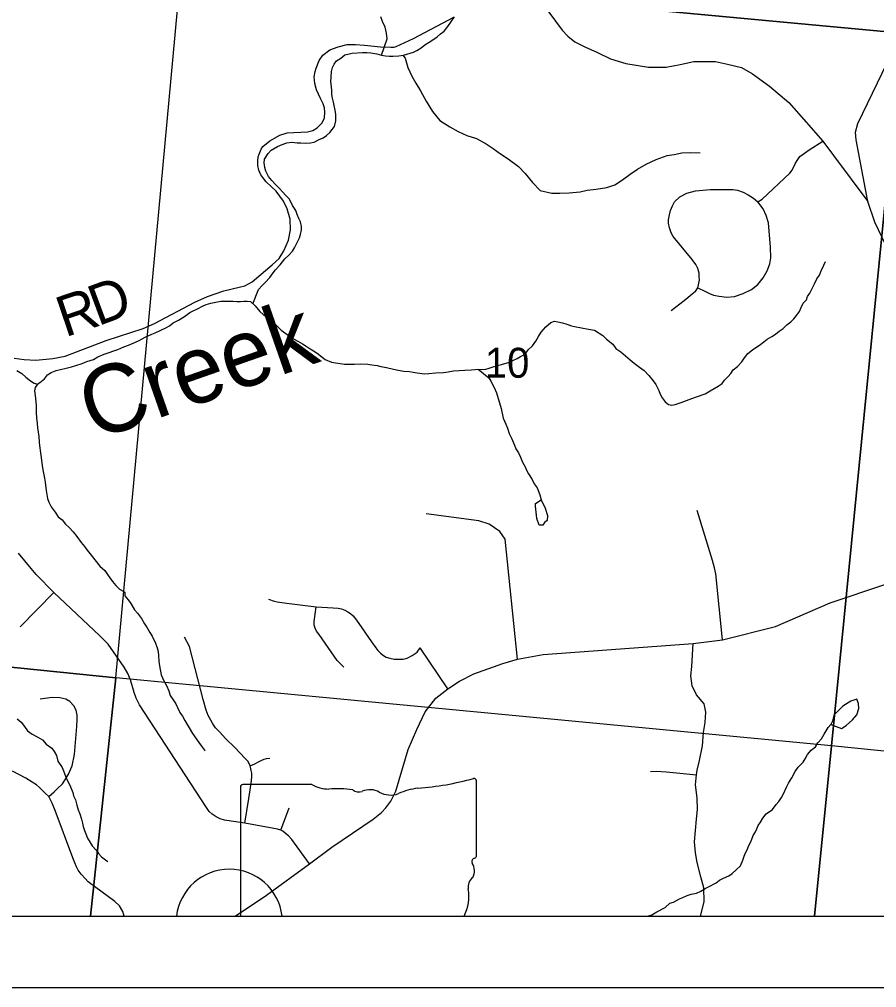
# Model space of a CAD drawing. Extents: x 0 to 34, y 0 to 22.
# Drawn here: x 2.941 to 4.14, y 14 to 15.353 of the extents above; entities that cross this region are included whole.
import ezdxf

# ---------------------------------------------------------------- set-up
doc = ezdxf.new("R2010")
doc.units = 0
for name, color, linetype in [('Default', 7, 'Continuous'), ('GM_X_County_Road', 7, 'Continuous'), ('GM_X_County_Road_Text', 7, 'Continuous'), ('GM_X_Major_Lake', 7, 'Continuous'), ('GM_X_Minor_Lake', 7, 'Continuous'), ('GM_X_Minor_River', 7, 'Continuous'), ('GM_X_Minor_River_Text', 7, 'Continuous'), ('GM_X_Section', 7, 'Continuous'), ('GM_X_Section_Text', 7, 'Continuous'), ('GM_X_State_Location', 7, 'Continuous'), ('GM_X_State_Route', 7, 'Continuous'), ('GM_X_Township_Road', 7, 'Continuous'), ('GM_X_Unincorporated_Text', 7, 'Continuous'), ('SH_Data', 7, 'Continuous')]:
    doc.layers.add(name, color=color, linetype=linetype)

msp = doc.modelspace()

# ---------------------------------------------------------------- linework, layer by layer
at = {"layer": 'Default'}
for points in [[(2.1, 14.8697), (2.1, 14.5322), (3.0761, 14.4328), (3.1681, 15.4277), (2.1629, 15.5646)], [(2.1, 14.5322), (2.1, 14.1), (3.0409, 14.1), (3.0761, 14.4328)], [(3.0409, 14.1), (4.0529, 14.1), (4.0766, 14.3377), (3.0761, 14.4328)], [(4.0529, 14.1), (5.0677, 14.1), (5.0822, 14.236), (4.0766, 14.3377)]]:
    msp.add_lwpolyline(points, close=True, dxfattribs=at)
at = {"layer": 'GM_X_County_Road'}
for points in [[(3.672, 15.3757), (3.7001, 15.338), (3.708, 15.3295), (3.7178, 15.3218), (3.7316, 15.3145), (3.7492, 15.3065), (3.7674, 15.2977), (3.789, 15.2914), (3.8205, 15.2861), (3.8455, 15.2864), (3.8651, 15.2899), (3.8842, 15.2941), (3.9145, 15.2941), (3.9313, 15.2905), (3.9506, 15.2856), (3.9658, 15.2768), (3.9896, 15.2596), (4.0169, 15.2367), (4.0411, 15.2093), (4.0641, 15.1826), (4.0793, 15.1628), (4.1274, 15.0987)], [(2.9342, 14.8796), (2.9481, 14.8779), (2.9642, 14.8767), (2.9883, 14.8789), (3.0052, 14.8824), (3.0625, 14.9041), (3.1142, 14.9212), (3.1302, 14.928), (3.1866, 14.9577), (3.2045, 14.9655), (3.2271, 14.9737), (3.2484, 14.9786), (3.2565, 14.9806), (3.2666, 14.9861), (3.2949, 15.0098), (3.3046, 15.0188), (3.3111, 15.0296), (3.3173, 15.0444), (3.3202, 15.0591), (3.32, 15.0738), (3.3158, 15.0882), (3.3105, 15.0988), (3.3004, 15.113), (3.2865, 15.126), (3.2818, 15.1319), (3.2788, 15.1358), (3.2761, 15.1422), (3.2747, 15.1489), (3.2748, 15.1549), (3.2753, 15.1608), (3.2764, 15.1647), (3.2794, 15.1718), (3.2817, 15.1752), (3.2913, 15.1833), (3.3054, 15.1911), (3.3158, 15.1944), (3.3442, 15.1956), (3.3514, 15.1979), (3.3575, 15.2013), (3.3647, 15.2085), (3.3676, 15.2152), (3.3685, 15.2231), (3.368, 15.2292), (3.366, 15.2351), (3.362, 15.2424), (3.3566, 15.2545), (3.3541, 15.2635), (3.3535, 15.2726), (3.3547, 15.2799), (3.3564, 15.2847), (3.3604, 15.2954), (3.3657, 15.3028), (3.3754, 15.3103), (3.3868, 15.3144), (3.3997, 15.3178), (3.411, 15.3178), (3.4239, 15.317), (3.4463, 15.3144), (3.4603, 15.314), (3.4645, 15.3143), (3.4666, 15.3146), (3.4679, 15.3149), (3.4921, 15.3261), (3.5487, 15.3559)], [(4.1721, 14.9965), (4.1372, 15.0695), (4.1274, 15.0987), (4.1107, 15.1848), (4.1099, 15.1955), (4.1132, 15.2073), (4.1748, 15.3344)]]:
    msp.add_lwpolyline(points, dxfattribs=at)
at = {"layer": 'GM_X_Major_Lake'}
msp.add_line((3.3503, 14.2839), (3.2538, 14.2839), dxfattribs=at)
for points in [[(3.5801, 14.1842), (3.5801, 14.1842), (3.5802, 14.1842), (3.5802, 14.289)], [(3.2506, 14.2804), (3.2506, 14.1), (3.563, 14.1)]]:
    msp.add_lwpolyline(points, dxfattribs=at)
for centre, major_axis, start_param, end_param in [((3.4628, 14.5567), (0.3495, 0), 4.814394, 5.042369), ((3.5765, 14.2893), (0.00367, 0), 6.197627, 7.989034), ((3.2543, 14.2809), (0.00382, 0), 1.727492, 3.291633), ((3.3733, 14.3071), (0.037, 0), 4.042888, 4.731792), ((3.3856, 14.1715), (0.133, 0), 1.404758, 1.657859), ((3.4158, 14.2819), (0.0107, 0), 3.836095, 5.185415), ((3.4315, 14.2588), (0.0222, 0), 0.950623, 2.079405), ((3.5073, 14.2228), (0.0703, 0), 1.699012, 2.107814), ((3.4601, 14.2905), (0.0267, 0), 4.08156, 5.145723), ((3.5793, 14.1765), (0.00568, 0), 1.883976, 3.671073), ((3.5762, 14.1838), (0.00393, 0), 5.054544, 6.418171), ((3.5432, 14.1632), (0.0341, 0), 5.934695, 6.695948), ((3.5933, 14.1404), (0.0248, 0), 2.387724, 3.262537), ((3.4823, 14.127), (0.0874, 0), 5.886245, 6.440018)]:
    msp.add_ellipse(centre, major_axis=major_axis, ratio=0.8, start_param=start_param, end_param=end_param, dxfattribs=at)
at = {"layer": 'GM_X_Minor_Lake'}
msp.add_line((3.6628, 14.6765), (3.6705, 14.6814), dxfattribs=at)
for points in [[(3.6705, 14.6814), (3.6761, 14.6699), (3.6796, 14.6599), (3.679, 14.6527), (3.6752, 14.6498), (3.6732, 14.6464), (3.6678, 14.6461), (3.6647, 14.6553), (3.664, 14.6603), (3.6629, 14.6729), (3.6628, 14.6765)], [(4.0756, 14.3678), (4.0905, 14.3621), (4.097, 14.3665), (4.1056, 14.3743), (4.1119, 14.3813), (4.1144, 14.39), (4.1142, 14.3972), (4.1117, 14.403), (4.1033, 14.4002), (4.0924, 14.3932), (4.0839, 14.3851)], [(4.0839, 14.3851), (4.0803, 14.381), (4.0778, 14.3723), (4.0756, 14.3678)]]:
    msp.add_lwpolyline(points, dxfattribs=at)
at = {"layer": 'GM_X_Minor_River'}
for points in [[(3.2677, 14.9557), (3.2758, 14.9754), (3.2805, 14.9809), (3.2848, 14.9853), (3.2915, 14.9923), (3.2959, 14.9986), (3.2991, 15.0031), (3.3058, 15.0101), (3.3125, 15.0182), (3.318, 15.0233), (3.3232, 15.0292), (3.326, 15.0337), (3.3301, 15.0419), (3.3329, 15.0475), (3.3342, 15.0524), (3.3356, 15.0588), (3.3357, 15.0637), (3.3344, 15.0702), (3.3319, 15.0749), (3.3295, 15.0803), (3.3278, 15.0857), (3.3231, 15.0927), (3.3188, 15.1016), (3.3137, 15.1067), (3.3093, 15.1121), (3.3049, 15.1168), (3.2987, 15.1228), (3.2943, 15.1279), (3.2895, 15.1333), (3.2856, 15.1407), (3.2843, 15.1461), (3.2834, 15.1525), (3.2839, 15.1578), (3.2891, 15.1656), (3.2935, 15.1704), (3.302, 15.1755), (3.3085, 15.1783), (3.3151, 15.1803), (3.3223, 15.1812), (3.3295, 15.1806), (3.3348, 15.1804), (3.3416, 15.1798), (3.3481, 15.1803), (3.3534, 15.1813), (3.3596, 15.1845), (3.3658, 15.1873), (3.3705, 15.1909), (3.3755, 15.1949), (3.3819, 15.2035), (3.3837, 15.211), (3.3836, 15.2201), (3.3827, 15.2262), (3.3814, 15.2327), (3.3804, 15.2373), (3.3791, 15.2427), (3.3781, 15.248), (3.3779, 15.2534), (3.3774, 15.2587), (3.3768, 15.2659), (3.3771, 15.2728), (3.3777, 15.28), (3.379, 15.2856), (3.3811, 15.2905), (3.3847, 15.2949), (3.3905, 15.2989), (3.3963, 15.3032), (3.4063, 15.3056), (3.4208, 15.3066), (3.4268, 15.3067), (3.4325, 15.3062), (3.4408, 15.3047), (3.4476, 15.303), (3.4529, 15.302), (3.4582, 15.3015), (3.4639, 15.3017), (3.4715, 15.3022), (3.4783, 15.3031), (3.4921, 15.3071), (3.4968, 15.3093), (3.503, 15.3132), (3.5081, 15.3176), (3.5139, 15.3212), (3.5205, 15.3255), (3.5251, 15.3284), (3.5299, 15.3328), (3.5349, 15.3364), (3.5401, 15.3431), (3.5445, 15.349), (3.5496, 15.3564)], [(3.4476, 15.303), (3.4556, 15.3259), (3.4547, 15.3339), (3.4524, 15.3423), (3.4488, 15.35), (3.4464, 15.3566)], [(3.4773, 15.3029), (3.4807, 15.2989), (3.4845, 15.2859), (3.4898, 15.2736), (3.4956, 15.2636), (3.5021, 15.2531), (3.5097, 15.2388), (3.5188, 15.2241), (3.529, 15.2117), (3.5428, 15.2026), (3.5548, 15.1961), (3.5668, 15.1909), (3.5803, 15.1863), (3.5938, 15.1791), (3.6035, 15.1727), (3.6139, 15.1652), (3.6244, 15.158), (3.6389, 15.1474), (3.6481, 15.1376), (3.6587, 15.1251), (3.6694, 15.1138), (3.6856, 15.1099), (3.6967, 15.11), (3.7096, 15.1104), (3.7252, 15.1122), (3.7351, 15.1142), (3.7477, 15.1158), (3.7622, 15.118), (3.7737, 15.1219), (3.7845, 15.1288), (3.795, 15.1368), (3.8055, 15.1438), (3.8175, 15.1506), (3.8313, 15.1571), (3.8467, 15.1627), (3.8566, 15.1643), (3.8673, 15.1663), (3.8798, 15.1671), (3.8931, 15.1663)], [(3.9758, 14.8976), (3.9817, 14.9023), (3.9864, 14.9063), (3.9929, 14.9099), (3.998, 14.9131), (4.0034, 14.9171), (4.0089, 14.9211), (4.014, 14.9263), (4.0194, 14.9303), (4.0238, 14.9347), (4.0277, 14.9391), (4.0317, 14.945), (4.0342, 14.9503), (4.037, 14.9562), (4.0414, 14.961), (4.0427, 14.9655), (4.0463, 14.9704), (4.0499, 14.9778), (4.0528, 14.9834), (4.0561, 14.9905), (4.0597, 14.9957), (4.0618, 15.0014), (4.0658, 15.0096), (4.0679, 15.0148)], [(2.9378, 14.8621), (2.9449, 14.8581), (2.9504, 14.8529), (2.957, 14.8481), (2.9619, 14.8446), (2.9667, 14.8432), (2.9718, 14.8469), (2.9765, 14.8509), (2.9805, 14.8565), (2.9859, 14.8597), (2.9928, 14.8621), (3.0005, 14.8641), (3.0051, 14.8651), (3.0143, 14.8674), (3.0204, 14.8695), (3.0289, 14.8723), (3.0358, 14.8747), (3.045, 14.8778), (3.0508, 14.8814), (3.0597, 14.8852), (3.067, 14.8873), (3.0735, 14.8897), (3.0789, 14.8918), (3.0874, 14.8953), (3.0939, 14.8977), (3.1035, 14.902), (3.1086, 14.9044), (3.1171, 14.9087), (3.1263, 14.9129), (3.1313, 14.9151), (3.146, 14.9218), (3.1514, 14.9246), (3.1565, 14.929), (3.1638, 14.9325), (3.1723, 14.9379), (3.1797, 14.9434), (3.1844, 14.9455), (3.1902, 14.9487), (3.1975, 14.9523), (3.2025, 14.9544), (3.209, 14.9564), (3.2182, 14.9584), (3.2228, 14.959), (3.2296, 14.9591), (3.2342, 14.9594), (3.2395, 14.9592), (3.2452, 14.9586), (3.2505, 14.9588), (3.2551, 14.959), (3.2596, 14.9592), (3.2646, 14.9587), (3.2708, 14.9528), (3.2774, 14.9446), (3.2862, 14.937), (3.2925, 14.9323), (3.3003, 14.9259), (3.3072, 14.9185), (3.3139, 14.914), (3.3194, 14.9097), (3.3243, 14.9065), (3.3306, 14.9032), (3.3373, 14.8996)], [(3.3373, 14.8996), (3.3421, 14.8963), (3.3477, 14.8927), (3.3548, 14.8883), (3.3592, 14.8851), (3.3644, 14.8811), (3.3688, 14.8779), (3.3774, 14.8742), (3.3831, 14.8729), (3.3899, 14.8719), (3.3959, 14.8713), (3.4035, 14.871), (3.4096, 14.8712), (3.418, 14.8717), (3.4286, 14.8713), (3.4339, 14.8704), (3.4414, 14.8693), (3.4467, 14.868), (3.4543, 14.8666), (3.4644, 14.8644), (3.4708, 14.863), (3.4788, 14.8616), (3.4867, 14.8609), (3.4916, 14.86), (3.4973, 14.8591), (3.5082, 14.8579), (3.5136, 14.8581), (3.5235, 14.8589), (3.5341, 14.8597), (3.5406, 14.8606), (3.5482, 14.8618), (3.5562, 14.8623), (3.5638, 14.8628), (3.5733, 14.8633), (3.5783, 14.8638), (3.5829, 14.8641), (3.5874, 14.8635), (3.5935, 14.8641), (3.5981, 14.8658), (3.6035, 14.8675), (3.6096, 14.8692), (3.6154, 14.8705), (3.62, 14.8719), (3.6249, 14.8736), (3.6373, 14.8793), (3.6419, 14.8818), (3.6485, 14.885), (3.6525, 14.8913), (3.6584, 14.8968), (3.6632, 14.9035), (3.6668, 14.9098), (3.6708, 14.9161), (3.6772, 14.9235), (3.6842, 14.9293), (3.6892, 14.9311), (3.6941, 14.9305), (3.7005, 14.9291), (3.7065, 14.927), (3.7129, 14.9249), (3.7174, 14.924), (3.7268, 14.9221), (3.7367, 14.9203), (3.7453, 14.9185), (3.7568, 14.9112), (3.762, 14.9061), (3.7709, 14.8993), (3.7752, 14.8931), (3.7822, 14.8883), (3.7885, 14.8828), (3.7952, 14.8772), (3.8007, 14.8725), (3.8081, 14.8669), (3.8144, 14.8621), (3.821, 14.8554), (3.8272, 14.848), (3.8308, 14.8426), (3.8351, 14.8344), (3.8368, 14.8294), (3.8396, 14.824), (3.844, 14.8185), (3.8488, 14.8146), (3.8533, 14.814), (3.8579, 14.815), (3.8664, 14.8178), (3.881, 14.8233), (3.8879, 14.8254), (3.8998, 14.8295), (3.9068, 14.8338), (3.918, 14.8403), (3.9235, 14.8443), (3.9267, 14.8487), (3.9318, 14.8539), (3.9357, 14.8583), (3.9389, 14.8631), (3.9452, 14.8679), (3.9511, 14.8745), (3.9547, 14.8801), (3.9595, 14.886), (3.9661, 14.8914), (3.9708, 14.8943), (3.9758, 14.8976)], [(3.5825, 14.864), (3.5976, 14.8522), (3.6005, 14.8475), (3.6048, 14.8386), (3.6083, 14.8313), (3.6148, 14.8094), (3.6173, 14.7956), (3.6212, 14.7875), (3.6237, 14.7817), (3.6257, 14.7741), (3.6293, 14.7678), (3.6335, 14.7582), (3.6352, 14.7528), (3.6388, 14.7474), (3.6417, 14.7412), (3.6445, 14.7343), (3.6484, 14.7277), (3.6501, 14.723), (3.653, 14.718), (3.658, 14.7099), (3.6609, 14.7041), (3.6649, 14.6986), (3.6687, 14.6886), (3.6705, 14.6814)], [(2.9667, 14.8432), (2.9632, 14.8384), (2.9626, 14.8339), (2.9632, 14.8274), (2.9646, 14.8141), (2.9648, 14.8091), (2.965, 14.8034), (2.9651, 14.7962), (2.966, 14.7882), (2.9669, 14.7821), (2.9684, 14.7699), (2.9689, 14.7622), (2.9695, 14.7577), (2.971, 14.7473), (2.972, 14.7409), (2.9734, 14.729), (2.9747, 14.721), (2.9766, 14.7118), (2.9772, 14.7061), (2.9787, 14.6946), (2.9806, 14.6836), (2.9827, 14.6785), (2.9859, 14.672), (2.9913, 14.6646), (2.9957, 14.658), (3.0012, 14.6536), (3.0056, 14.6477), (3.0111, 14.643), (3.0166, 14.6367), (3.0217, 14.6305), (3.0278, 14.6219), (3.0326, 14.6164), (3.0362, 14.6113), (3.0417, 14.6043), (3.0468, 14.598), (3.054, 14.5891), (3.0607, 14.5827), (3.0647, 14.5773), (3.0679, 14.5726), (3.0715, 14.5676), (3.0763, 14.5621), (3.0814, 14.5569), (3.0874, 14.5533), (3.0886, 14.5527)], [(3.0886, 14.5527), (3.0887, 14.5476), (3.0934, 14.5417), (3.097, 14.5366), (3.1021, 14.5281), (3.1065, 14.5234), (3.1119, 14.5156), (3.1162, 14.5082), (3.1198, 14.5028), (3.1237, 14.4962), (3.127, 14.4912), (3.1316, 14.4811), (3.134, 14.4749), (3.1354, 14.4696), (3.1359, 14.4635), (3.1364, 14.4562), (3.1373, 14.4497), (3.1396, 14.4371), (3.1431, 14.4287), (3.147, 14.4221), (3.1502, 14.4147), (3.1522, 14.4082), (3.1562, 14.402), (3.1598, 14.3965), (3.1623, 14.3915), (3.1658, 14.3845), (3.1695, 14.3795), (3.1727, 14.3733), (3.1759, 14.3675), (3.1788, 14.3628), (3.1834, 14.355), (3.1921, 14.3426), (3.1961, 14.3375), (3.2001, 14.3317), (3.2008, 14.3307)], [(2.9385, 14.3757), (2.9437, 14.371), (2.9484, 14.3647), (2.9527, 14.3589), (2.9594, 14.3541), (2.9672, 14.35), (2.9736, 14.3464), (2.9787, 14.3401), (2.9868, 14.3345), (2.9901, 14.3298), (2.9933, 14.3244), (2.9953, 14.3163), (3.0011, 14.3074), (3.0032, 14.3028), (3.0074, 14.2916), (3.012, 14.2831), (3.0162, 14.2727), (3.0172, 14.2681), (3.02, 14.2623)], [(3.8192, 14.1), (3.8193, 14.1), (3.8254, 14.1017), (3.8324, 14.1057), (3.844, 14.1121), (3.8506, 14.118), (3.8556, 14.1193), (3.8641, 14.124), (3.8688, 14.1261), (3.8746, 14.1289), (3.8803, 14.1306), (3.8876, 14.1319), (3.8937, 14.1347), (3.8999, 14.1383), (3.9046, 14.1408), (3.9154, 14.1465), (3.9201, 14.1501), (3.9255, 14.153), (3.9328, 14.1562), (3.9375, 14.1594), (3.9434, 14.1645), (3.9492, 14.17), (3.9526, 14.1779), (3.9543, 14.1835), (3.9563, 14.1884), (3.9588, 14.1933), (3.9604, 14.1978), (3.9633, 14.203), (3.965, 14.2075), (3.967, 14.2127), (3.9702, 14.2176), (3.9723, 14.2221), (3.974, 14.2266), (3.9772, 14.2314), (3.9804, 14.2366), (3.9852, 14.2429), (3.9941, 14.249), (3.9989, 14.2557), (4.0028, 14.2601), (4.0065, 14.2657), (4.0093, 14.2709), (4.0134, 14.2799), (4.0163, 14.2859), (4.0211, 14.293), (4.0255, 14.3019), (4.0299, 14.3082), (4.037, 14.3152), (4.0398, 14.3197), (4.0431, 14.3256), (4.0478, 14.3316), (4.0541, 14.3363), (4.0573, 14.3419), (4.0624, 14.3478), (4.0661, 14.3541), (4.0717, 14.3634), (4.0756, 14.3678)], [(3.02, 14.2623), (3.0217, 14.255), (3.0237, 14.2485), (3.0258, 14.2427), (3.0282, 14.2354), (3.0295, 14.2296), (3.0305, 14.2251), (3.0322, 14.2197), (3.0343, 14.215), (3.0364, 14.2089), (3.0404, 14.203), (3.0432, 14.198), (3.0487, 14.1921), (3.052, 14.1874), (3.056, 14.1827), (3.0634, 14.1772), (3.0652, 14.176)]]:
    msp.add_lwpolyline(points, dxfattribs=at)
at = {"layer": 'GM_X_Section'}
for points in [[(3.2644, 16.338), (3.276, 16.3476), (3.3136, 16.3694), (3.3687, 16.3893), (4.2789, 16.3058), (4.1746, 15.3336), (3.1681, 15.4277)], [(4.1746, 15.3336), (4.0766, 14.3377), (3.0761, 14.4328), (3.1681, 15.4277)], [(5.1838, 15.2208), (5.0822, 14.236), (4.0766, 14.3377), (4.1746, 15.3336)]]:
    msp.add_lwpolyline(points, close=True, dxfattribs=at)
at = {"layer": 'GM_X_State_Route'}
for points in [[(2.1, 16.7408), (2.1, 14.1), (5.0661, 14.1), (5.1035, 14.4713), (5.1456, 14.8898), (5.1715, 15.1469), (5.2499, 15.926)], [(3.2429, 14.1), (3.2869, 14.1291), (3.347, 14.1732), (3.378, 14.1965), (3.4358, 14.2354), (3.4475, 14.2446), (3.4537, 14.2514), (3.4606, 14.2605), (3.4677, 14.2744), (3.4722, 14.2905), (3.4847, 14.3327), (3.497, 14.3608), (3.5087, 14.3855), (3.5233, 14.4043), (3.5403, 14.4176), (3.5563, 14.428), (3.5767, 14.4386), (3.6169, 14.4529), (3.6374, 14.4592), (3.6735, 14.4657), (3.8833, 14.4807), (3.9243, 14.4859), (3.9982, 14.5046), (4.0744, 14.5377), (4.1512, 14.5633)]]:
    msp.add_lwpolyline(points, dxfattribs=at)
at = {"layer": 'GM_X_Township_Road'}
for p, q in [((2.9424, 14.504), (2.9896, 14.5522)), ((3.5403, 14.4176), (3.5016, 14.4748)), ((3.3066, 14.2199), (3.3186, 14.2514))]:
    msp.add_line(p, q, dxfattribs=at)
for points in [[(3.8524, 14.9461), (3.8644, 14.9554), (3.8729, 14.9621), (3.8791, 14.9671), (3.8868, 14.9736), (3.8898, 14.978), (3.8921, 14.9884), (3.8916, 14.9942), (3.8914, 14.9985), (3.8895, 15.005), (3.887, 15.0105), (3.8819, 15.0172), (3.8551, 15.0498), (3.8524, 15.0549), (3.8498, 15.0616), (3.8484, 15.0683), (3.8487, 15.0729), (3.8498, 15.0798), (3.8512, 15.0861), (3.854, 15.0923), (3.8572, 15.0978), (3.8646, 15.105), (3.8743, 15.1101), (3.8863, 15.1133), (3.9069, 15.1154), (3.9383, 15.1152), (3.9452, 15.1142), (3.953, 15.1115), (3.96, 15.108), (3.9674, 15.1031), (3.9734, 15.0981), (3.9794, 15.1018), (4.0184, 15.138), (4.0216, 15.1424), (4.0262, 15.1521), (4.0286, 15.1558), (4.032, 15.1613), (4.0454, 15.1708), (4.0641, 15.1826)], [(3.8898, 14.978), (3.8995, 14.9731), (3.9059, 14.9701), (3.9117, 14.9678), (3.9196, 14.966), (3.9302, 14.9648), (3.9408, 14.9657), (3.953, 14.9697), (3.9646, 14.9757), (3.9736, 14.9826), (3.9808, 14.9918), (3.9863, 15.0015), (3.9902, 15.0115), (3.9918, 15.0198), (3.9914, 15.0346), (3.9886, 15.0685), (3.9851, 15.0791), (3.9808, 15.0881), (3.9734, 15.0981)], [(3.9243, 14.4859), (3.9146, 14.5783), (3.9128, 14.5868), (3.91, 14.5968), (3.8887, 14.6669)], [(3.6374, 14.4592), (3.6204, 14.6268), (3.6128, 14.6373), (3.598, 14.6475), (3.5835, 14.6521), (3.5097, 14.662)], [(3.347, 14.1732), (3.3222, 14.2069), (3.3177, 14.2122), (3.3135, 14.2156), (3.3095, 14.2185), (3.3066, 14.2199), (3.302, 14.2215), (3.2564, 14.2297), (3.228, 14.2342), (3.2222, 14.2361), (3.2166, 14.2385), (3.211, 14.2422), (3.2068, 14.2461), (3.202, 14.2531), (3.1093, 14.3953), (3.1048, 14.4046), (3.1019, 14.4126), (3.0966, 14.4301), (3.0929, 14.4391), (3.0876, 14.4479), (3.0653, 14.48), (3.061, 14.4848), (3.0539, 14.4917), (2.9896, 14.5522), (2.9647, 14.5774), (2.9578, 14.5856), (2.9403, 14.6069)], [(3.2894, 14.543), (3.2977, 14.5401), (3.3016, 14.539), (3.3115, 14.5377), (3.3561, 14.5323), (3.3801, 14.5305), (3.3869, 14.5302), (3.3918, 14.5291), (3.3961, 14.5273), (3.4002, 14.525), (3.404, 14.5228), (3.408, 14.5194), (3.4112, 14.5153), (3.4157, 14.5088), (3.4335, 14.4832), (3.4394, 14.475), (3.4425, 14.471), (3.4463, 14.4674), (3.4504, 14.4643), (3.4542, 14.4618), (3.4589, 14.4602), (3.465, 14.4589), (3.4709, 14.4588), (3.4778, 14.4589), (3.4833, 14.4606), (3.4904, 14.4642), (3.4974, 14.4687), (3.5016, 14.4748)], [(3.395, 14.4478), (3.3853, 14.4571), (3.3603, 14.4933), (3.3567, 14.4983), (3.3547, 14.5025), (3.3536, 14.5066), (3.3534, 14.5117), (3.3561, 14.5323)], [(3.2637, 14.3097), (3.2629, 14.3124), (3.2606, 14.3164), (3.2566, 14.3207), (3.2429, 14.3351), (3.2296, 14.3483), (3.2213, 14.3571), (3.2157, 14.3629), (3.2118, 14.3684), (3.2091, 14.3736), (3.2054, 14.3803), (3.2024, 14.3875), (3.1983, 14.4025), (3.1906, 14.4314), (3.179, 14.4767), (3.172, 14.4899)], [(3.8934, 14.1), (3.8984, 14.12), (3.8982, 14.1394), (3.8939, 14.1547), (3.8885, 14.1748), (3.8864, 14.1883), (3.885, 14.2036), (3.8876, 14.2353), (3.889, 14.249), (3.8885, 14.2653), (3.8864, 14.2834), (3.8878, 14.2972), (3.8885, 14.304), (3.8921, 14.3172), (3.8961, 14.3378), (3.8977, 14.3567), (3.8999, 14.3704), (3.9003, 14.3781), (3.901, 14.385), (3.8984, 14.3966), (3.8878, 14.4091), (3.8817, 14.4216), (3.88, 14.4355), (3.8814, 14.4485), (3.8833, 14.4807)], [(2.9823, 14.2673), (2.9861, 14.2702), (2.99, 14.2738), (2.9942, 14.2778), (3.0014, 14.285), (3.0057, 14.2911), (3.0099, 14.2981), (3.0152, 14.3097), (3.0185, 14.3256), (3.0216, 14.3651), (3.0222, 14.3745), (3.0223, 14.3805), (3.0209, 14.3879), (3.0175, 14.3937), (3.0121, 14.3999), (3.0061, 14.4032), (2.9977, 14.405), (2.987, 14.4053), (2.9706, 14.4033)], [(3.2637, 14.3097), (3.2704, 14.3129), (3.2755, 14.3155), (3.2802, 14.3178), (3.2833, 14.3191), (3.2867, 14.3201), (3.2914, 14.3207)], [(3.0876, 14.1), (3.0861, 14.1063), (3.0812, 14.1142), (3.0747, 14.1204), (3.0377, 14.1479), (3.034, 14.152), (3.0276, 14.1585), (3.0236, 14.1642), (3.0211, 14.1689), (3.0188, 14.1743), (3.016, 14.1816), (2.9916, 14.2474), (2.9872, 14.2578), (2.9823, 14.2673), (2.9775, 14.2718), (2.9734, 14.276), (2.9695, 14.2796), (2.9653, 14.2834), (2.9592, 14.2871), (2.9504, 14.2928), (2.9319, 14.3024)], [(3.2564, 14.2297), (3.2621, 14.2645), (3.2638, 14.2763), (3.2657, 14.289), (3.2663, 14.295), (3.2661, 14.2999), (3.2655, 14.3034), (3.2642, 14.3082), (3.2637, 14.3097)], [(3.8233, 14.302), (3.8316, 14.3023), (3.8457, 14.3015), (3.8878, 14.2972)]]:
    msp.add_lwpolyline(points, dxfattribs=at)
at = {"layer": 'GM_X_Unincorporated_Text'}
msp.add_line((3.161, 14.1), (3.3087, 14.1), dxfattribs=at)
msp.add_arc((3.2348, 14.091), 0.0744, 6.9741, 173.0259, dxfattribs=at)
at = {"layer": 'SH_Data'}
for p, q in [((2.1, 14.1), (8.9, 14.1)), ((2, 14), (9, 14))]:
    msp.add_line(p, q, dxfattribs=at)

# ---------------------------------------------------------------- texts
at = {"layer": 'GM_X_County_Road_Text'}
for s, rotation, p in [('D', 20.3891, (3.0512, 14.924)), ('R', 18.7429, (3.0053, 14.9084))]:
    msp.add_text(s, height=0.0568, rotation=rotation, dxfattribs=at).set_placement(p)
at = {"layer": 'GM_X_Minor_River_Text'}
msp.add_text('Creek', height=0.09468, rotation=19.2829, dxfattribs=at).set_placement((3.0455, 14.7638))
at = {"layer": 'GM_X_Section_Text'}
msp.add_text('10', height=0.04186, rotation=0, dxfattribs=at).set_placement((3.5919, 14.8522))
at = {"layer": 'GM_X_State_Location'}
for s in ['s', 'r']:
    msp.add_text(s, height=0.000189, dxfattribs=at).set_placement((3.4117, 14.1671))
msp.add_text('264', height=0.000189, rotation=0, dxfattribs=at).set_placement((3.3448, 14.1533))

doc.saveas('drawing.dxf')
